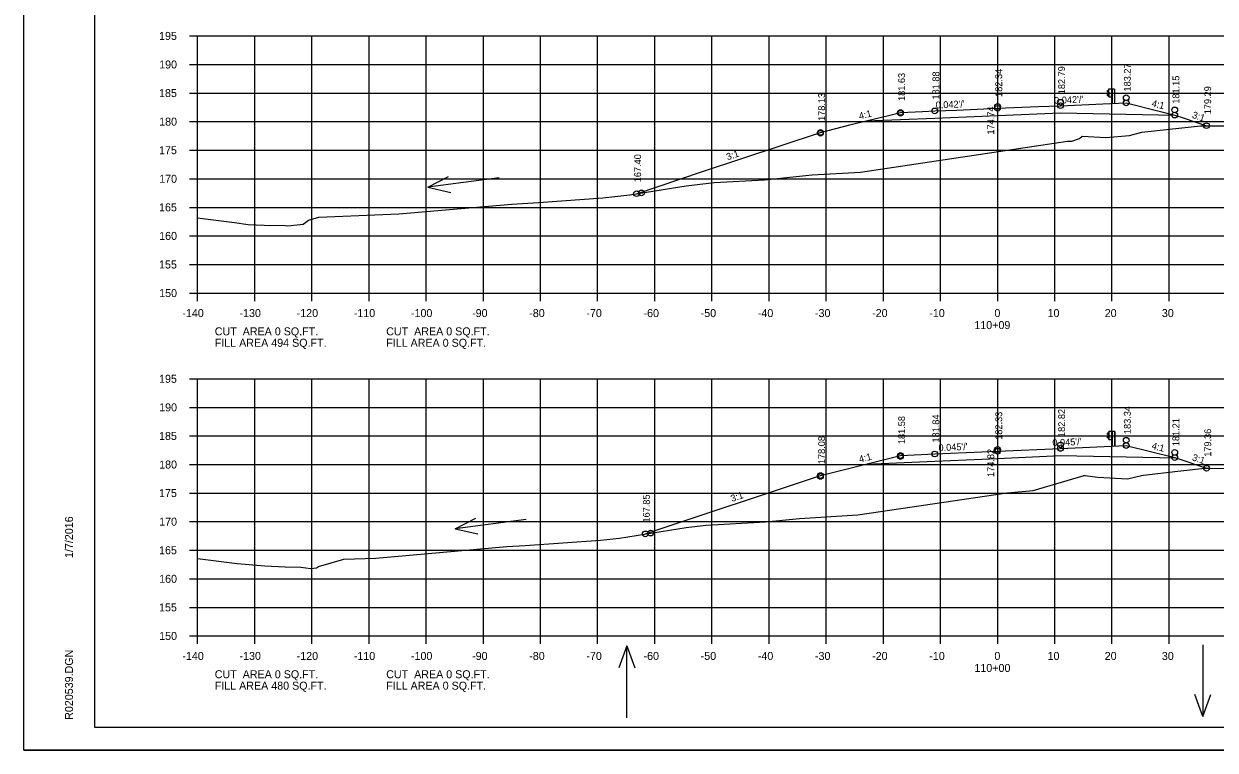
# Model space of a CAD drawing. Extents: x 915787 to 919910, y 133456 to 136717.
# Drawn here: x 916243.6 to 916452, y 134309.4 to 134436.5 of the extents above; entities that cross this region are included whole.
import ezdxf

# ---------------------------------------------------------------- set-up
doc = ezdxf.new("R2010")
doc.units = 0
for name, color, linetype in [('R_Axis', 7, 'Continuous'), ('R_Axis Annot', 7, 'Continuous'), ('R_Border', 7, 'Continuous'), ('R_Border Notes', 7, 'Continuous'), ('R_Exist Surface', 7, 'Continuous'), ('R_Fin Surface', 7, 'Continuous'), ('R_Grid', 7, 'Continuous'), ('R_No Plot', 7, 'Continuous'), ('R_Proposed Road', 7, 'Continuous'), ('R_Water Annot', 7, 'Continuous'), ('R_Xsect Elev', 7, 'Continuous'), ('R_Xsect Slope', 7, 'Continuous')]:
    doc.layers.add(name, color=color, linetype=linetype)

msp = doc.modelspace()

# ---------------------------------------------------------------- linework, layer by layer
at = {"layer": 'R_Axis'}
for p, q in [((916272.58, 134434.37), (916273.98, 134434.37)), ((916273.98, 134389.37), (916273.98, 134434.37)), ((916272.58, 134429.37), (916273.98, 134429.37)), ((916272.58, 134424.37), (916273.98, 134424.37)), ((916272.58, 134419.37), (916273.98, 134419.37)), ((916272.58, 134414.37), (916273.98, 134414.37)), ((916272.58, 134409.37), (916273.98, 134409.37)), ((916272.58, 134404.37), (916273.98, 134404.37)), ((916272.58, 134399.37), (916273.98, 134399.37)), ((916272.58, 134394.37), (916273.98, 134394.37)), ((916272.58, 134389.37), (916273.98, 134389.37)), ((916273.98, 134389.37), (916553.98, 134389.37)), ((916273.98, 134387.97), (916273.98, 134389.37)), ((916283.98, 134387.97), (916283.98, 134389.37)), ((916293.98, 134387.97), (916293.98, 134389.37)), ((916303.98, 134387.97), (916303.98, 134389.37)), ((916313.98, 134387.97), (916313.98, 134389.37)), ((916323.98, 134387.97), (916323.98, 134389.37)), ((916333.98, 134387.97), (916333.98, 134389.37)), ((916343.98, 134387.97), (916343.98, 134389.37)), ((916353.98, 134387.97), (916353.98, 134389.37)), ((916363.98, 134387.97), (916363.98, 134389.37)), ((916373.98, 134387.97), (916373.98, 134389.37)), ((916383.98, 134387.97), (916383.98, 134389.37)), ((916393.98, 134387.97), (916393.98, 134389.37)), ((916403.98, 134387.97), (916403.98, 134389.37)), ((916413.98, 134387.97), (916413.98, 134389.37)), ((916423.98, 134387.97), (916423.98, 134389.37)), ((916433.98, 134387.97), (916433.98, 134389.37)), ((916443.98, 134387.97), (916443.98, 134389.37)), ((916272.58, 134374.37), (916273.98, 134374.37)), ((916273.98, 134329.37), (916273.98, 134374.37)), ((916272.58, 134369.37), (916273.98, 134369.37)), ((916272.58, 134364.37), (916273.98, 134364.37)), ((916272.58, 134359.37), (916273.98, 134359.37)), ((916272.58, 134354.37), (916273.98, 134354.37)), ((916272.58, 134349.37), (916273.98, 134349.37)), ((916272.58, 134344.37), (916273.98, 134344.37)), ((916272.58, 134339.37), (916273.98, 134339.37)), ((916272.58, 134334.37), (916273.98, 134334.37)), ((916272.58, 134329.37), (916273.98, 134329.37)), ((916273.98, 134329.37), (916553.98, 134329.37)), ((916273.98, 134327.97), (916273.98, 134329.37)), ((916283.98, 134327.97), (916283.98, 134329.37)), ((916293.98, 134327.97), (916293.98, 134329.37)), ((916303.98, 134327.97), (916303.98, 134329.37)), ((916313.98, 134327.97), (916313.98, 134329.37)), ((916323.98, 134327.97), (916323.98, 134329.37)), ((916333.98, 134327.97), (916333.98, 134329.37)), ((916343.98, 134327.97), (916343.98, 134329.37)), ((916353.98, 134327.97), (916353.98, 134329.37)), ((916363.98, 134327.97), (916363.98, 134329.37)), ((916373.98, 134327.97), (916373.98, 134329.37)), ((916383.98, 134327.97), (916383.98, 134329.37)), ((916393.98, 134327.97), (916393.98, 134329.37)), ((916403.98, 134327.97), (916403.98, 134329.37)), ((916413.98, 134327.97), (916413.98, 134329.37)), ((916423.98, 134327.97), (916423.98, 134329.37)), ((916433.98, 134327.97), (916433.98, 134329.37)), ((916443.98, 134327.97), (916443.98, 134329.37))]:
    msp.add_line(p, q, dxfattribs=at)
at = {"layer": 'R_Border'}
for p, q in [((916255.98, 134313.37), (916255.98, 134518.83)), ((916255.98, 134313.37), (916255.98, 134313.37)), ((916572.16, 134313.37), (916255.98, 134313.37))]:
    msp.add_line(p, q, dxfattribs=at)
at = {"layer": 'R_Exist Surface'}
for points in [[(916273.98, 134402.53), (916280.41, 134401.69), (916282.85, 134401.35), (916285.65, 134401.27), (916289.3, 134401.22), (916289.75, 134401.16), (916292.42, 134401.45), (916293.41, 134402.15), (916295.18, 134402.65), (916309.18, 134403.23), (916328.94, 134404.94), (916333.63, 134405.24), (916344.9, 134406.02), (916349.64, 134406.57), (916359.49, 134408.14), (916364.37, 134408.7), (916373.17, 134409.2), (916381.49, 134410.04), (916389.97, 134410.53), (916426.22, 134415.93), (916426.93, 134415.98), (916428.32, 134416.39), (916428.75, 134416.83), (916432.88, 134416.58), (916437.03, 134416.95), (916439.21, 134417.53), (916444.03, 134418.04), (916449.5, 134418.66), (916455.2, 134418.65)], [(916273.98, 134342.94), (916280.91, 134342.07), (916285.77, 134341.65), (916289.29, 134341.45), (916292.03, 134341.42), (916293.81, 134341.16), (916294.8, 134341.27), (916295.16, 134341.53), (916299.56, 134342.78), (916305.17, 134343.01), (916328.09, 134345), (916331.27, 134345.2), (916344.49, 134346.12), (916347.82, 134346.5), (916359.45, 134348.36), (916362.89, 134348.76), (916373.34, 134349.35), (916379.3, 134349.95), (916389.49, 134350.54), (916415.63, 134354.43), (916420.18, 134354.8), (916429.1, 134357.45), (916429.13, 134357.48), (916429.26, 134357.45), (916431.51, 134357.13), (916436.67, 134356.86), (916439.16, 134357.44), (916439.51, 134357.51), (916445.5, 134358.19), (916450.19, 134358.73), (916450.82, 134358.72), (916456.38, 134358.62)]]:
    msp.add_lwpolyline(points, dxfattribs=at)
at = {"layer": 'R_Fin Surface'}
for points in [[(916350.78, 134406.76), (916362.34, 134410.62), (916382.97, 134417.49), (916388.1, 134418.78), (916390.97, 134419.49), (916394.85, 134420.46), (916396.97, 134420.99), (916400.83, 134421.16), (916402.97, 134421.24), (916406.86, 134421.4), (916413.97, 134421.7), (916421.04, 134422), (916424.97, 134422.16), (916432.36, 134422.47), (916436.47, 134422.64), (916442.47, 134421.14), (916444.97, 134420.51), (916444.99, 134420.51), (916446.59, 134419.97), (916450.53, 134418.66)], [(916390.97, 134419.49), (916402.97, 134419.99), (916413.97, 134420.45), (916424.97, 134420.91), (916444.99, 134420.51)], [(916352.31, 134347.22), (916382.97, 134357.44), (916390.89, 134359.42), (916396.97, 134360.94), (916402.97, 134361.21), (916413.97, 134361.7), (916424.97, 134362.19), (916436.47, 134362.7), (916444.97, 134360.58), (916445.14, 134360.54), (916450.52, 134358.73)], [(916390.89, 134359.42), (916402.97, 134359.96), (916413.97, 134360.45), (916424.97, 134360.94), (916445.14, 134360.54)]]:
    msp.add_lwpolyline(points, dxfattribs=at)
at = {"layer": 'R_Grid'}
for p, q in [((916273.98, 134434.37), (916553.98, 134434.37)), ((916273.98, 134389.37), (916273.98, 134434.37)), ((916283.98, 134389.37), (916283.98, 134434.37)), ((916293.98, 134389.37), (916293.98, 134434.37)), ((916303.98, 134389.37), (916303.98, 134434.37)), ((916313.98, 134389.37), (916313.98, 134434.37)), ((916323.98, 134389.37), (916323.98, 134434.37)), ((916333.98, 134389.37), (916333.98, 134434.37)), ((916343.98, 134389.37), (916343.98, 134434.37)), ((916353.98, 134389.37), (916353.98, 134434.37)), ((916363.98, 134389.37), (916363.98, 134434.37)), ((916373.98, 134389.37), (916373.98, 134434.37)), ((916383.98, 134389.37), (916383.98, 134434.37)), ((916393.98, 134389.37), (916393.98, 134434.37)), ((916403.98, 134389.37), (916403.98, 134434.37)), ((916413.98, 134389.37), (916413.98, 134434.37)), ((916423.98, 134389.37), (916423.98, 134434.37)), ((916433.98, 134389.37), (916433.98, 134434.37)), ((916443.98, 134389.37), (916443.98, 134434.37)), ((916273.98, 134429.37), (916553.98, 134429.37)), ((916273.98, 134424.37), (916553.98, 134424.37)), ((916273.98, 134419.37), (916553.98, 134419.37)), ((916273.98, 134414.37), (916553.98, 134414.37)), ((916273.98, 134409.37), (916553.98, 134409.37)), ((916273.98, 134404.37), (916553.98, 134404.37)), ((916273.98, 134399.37), (916553.98, 134399.37)), ((916273.98, 134394.37), (916553.98, 134394.37)), ((916273.98, 134389.37), (916553.98, 134389.37)), ((916273.98, 134374.37), (916553.98, 134374.37)), ((916273.98, 134329.37), (916273.98, 134374.37)), ((916283.98, 134329.37), (916283.98, 134374.37)), ((916293.98, 134329.37), (916293.98, 134374.37)), ((916303.98, 134329.37), (916303.98, 134374.37)), ((916313.98, 134329.37), (916313.98, 134374.37)), ((916323.98, 134329.37), (916323.98, 134374.37)), ((916333.98, 134329.37), (916333.98, 134374.37)), ((916343.98, 134329.37), (916343.98, 134374.37)), ((916353.98, 134329.37), (916353.98, 134374.37)), ((916363.98, 134329.37), (916363.98, 134374.37)), ((916373.98, 134329.37), (916373.98, 134374.37)), ((916383.98, 134329.37), (916383.98, 134374.37)), ((916393.98, 134329.37), (916393.98, 134374.37)), ((916403.98, 134329.37), (916403.98, 134374.37)), ((916413.98, 134329.37), (916413.98, 134374.37)), ((916423.98, 134329.37), (916423.98, 134374.37)), ((916433.98, 134329.37), (916433.98, 134374.37)), ((916443.98, 134329.37), (916443.98, 134374.37)), ((916273.98, 134369.37), (916553.98, 134369.37)), ((916273.98, 134364.37), (916553.98, 134364.37)), ((916273.98, 134359.37), (916553.98, 134359.37)), ((916273.98, 134354.37), (916553.98, 134354.37)), ((916273.98, 134349.37), (916553.98, 134349.37)), ((916273.98, 134344.37), (916553.98, 134344.37)), ((916273.98, 134339.37), (916553.98, 134339.37)), ((916273.98, 134334.37), (916553.98, 134334.37)), ((916273.98, 134329.37), (916553.98, 134329.37))]:
    msp.add_line(p, q, dxfattribs=at)
at = {"layer": 'R_No Plot'}
msp.add_line((916243.57, 134309.39), (916576.91, 134309.39), dxfattribs=at)
for points in [[(916243.57, 134522.72), (916576.91, 134522.72), (916576.91, 134309.38), (916243.57, 134309.38)], [(916489.9, 134518.83), (916489.9, 134508.95), (916525.63, 134508.95), (916525.63, 134506.03), (916548.83, 134506.03), (916548.83, 134482.81), (916572.16, 134482.81), (916572.16, 134313.37), (916255.98, 134313.37), (916255.98, 134518.83)]]:
    msp.add_lwpolyline(points, close=True, dxfattribs=at)
for centre in [(916436.47, 134423.55), (916396.97, 134420.99), (916396.97, 134420.83), (916402.97, 134421.24), (916402.97, 134421.24), (916413.97, 134422), (916413.97, 134421.7), (916424.97, 134422.76), (916424.97, 134422.16), (916436.47, 134422.64), (916444.97, 134421.42), (916444.97, 134420.51), (916382.97, 134417.49), (916382.97, 134417.33), (916450.53, 134418.66), (916350.78, 134406.76), (916351.66, 134406.89), (916424.97, 134362.79), (916436.47, 134363.61), (916436.47, 134362.7), (916396.97, 134360.94), (916396.97, 134360.78), (916402.97, 134361.21), (916402.97, 134361.21), (916413.97, 134362), (916413.97, 134361.7), (916424.97, 134362.19), (916444.97, 134361.49), (916444.97, 134360.58), (916450.54, 134358.72), (916382.97, 134357.44), (916382.97, 134357.28), (916352.31, 134347.22), (916353.24, 134347.37)]:
    msp.add_circle(centre, 0.5, dxfattribs=at)
at = {"layer": 'R_Proposed Road'}
for p, q in [((916433.28, 134423.91), (916433.15, 134424.02)), ((916433.16, 134424.75), (916433.29, 134424.86)), ((916433.33, 134424.51), (916433.16, 134424.61)), ((916433.17, 134424.74), (916433.3, 134424.84)), ((916433.34, 134424.53), (916433.17, 134424.63)), ((916433.29, 134423.92), (916433.17, 134424.03)), ((916433.18, 134424.17), (916433.34, 134424.27)), ((916433.19, 134424.15), (916433.35, 134424.25)), ((916433.39, 134423.85), (916433.28, 134423.91)), ((916433.29, 134424.86), (916433.4, 134424.92)), ((916433.4, 134423.87), (916433.29, 134423.92)), ((916433.3, 134424.84), (916433.39, 134424.89)), ((916433.37, 134424.33), (916433.37, 134424.46)), ((916433.39, 134424.33), (916433.39, 134424.46)), ((916433.43, 134423.71), (916433.43, 134425.07)), ((916433.44, 134424.33), (916433.44, 134424.45)), ((916433.44, 134424.45), (916433.49, 134424.45)), ((916433.44, 134424.42), (916433.49, 134424.42)), ((916433.44, 134424.36), (916433.49, 134424.36)), ((916433.44, 134424.36), (916433.49, 134424.36)), ((916433.44, 134424.33), (916433.49, 134424.33)), ((916433.5, 134424.34), (916433.5, 134424.44)), ((916433.92, 134424.77), (916433.87, 134424.77)), ((916433.87, 134424.77), (916433.87, 134424.64)), ((916433.87, 134424.7), (916433.93, 134424.7)), ((916433.92, 134424.64), (916433.87, 134424.64)), ((916433.87, 134423.96), (916433.87, 134424.08)), ((916433.87, 134424.08), (916433.92, 134424.08)), ((916433.87, 134424.02), (916433.93, 134424.02)), ((916433.87, 134423.96), (916433.92, 134423.96)), ((916433.93, 134425.07), (916433.94, 134425.07)), ((916433.93, 134425.07), (916434, 134425.07)), ((916433.93, 134423.71), (916433.96, 134423.71)), ((916433.96, 134422.56), (916433.96, 134425.07)), ((916434, 134424.65), (916434, 134424.77)), ((916434, 134424.77), (916434.05, 134424.77)), ((916434, 134424.74), (916434.05, 134424.74)), ((916434, 134424.68), (916434.04, 134424.68)), ((916434, 134424.68), (916434.05, 134424.68)), ((916434, 134424.65), (916434.05, 134424.65)), ((916434.01, 134423.96), (916434.01, 134424.08)), ((916434.01, 134424.08), (916434.06, 134424.08)), ((916434.01, 134424.05), (916434.06, 134424.05)), ((916434.01, 134423.99), (916434.05, 134423.99)), ((916434.01, 134423.99), (916434.06, 134423.99)), ((916434.01, 134423.96), (916434.06, 134423.96)), ((916434.05, 134424.66), (916434.05, 134424.76)), ((916434.06, 134423.97), (916434.06, 134424.07)), ((916434.42, 134425.07), (916434.42, 134422.56)), ((916434.45, 134425.07), (916434.45, 134422.56)), ((916433.29, 134364.92), (916433.4, 134364.98)), ((916433.44, 134363.77), (916433.44, 134365.13)), ((916433.93, 134365.14), (916433.94, 134365.14)), ((916433.93, 134365.14), (916434, 134365.14)), ((916433.97, 134362.62), (916433.97, 134365.14)), ((916434.43, 134365.14), (916434.43, 134362.62)), ((916434.46, 134365.14), (916434.46, 134362.62)), ((916433.16, 134364.82), (916433.29, 134364.92)), ((916433.34, 134364.57), (916433.16, 134364.67)), ((916433.29, 134363.97), (916433.16, 134364.08)), ((916433.17, 134364.8), (916433.3, 134364.91)), ((916433.3, 134363.99), (916433.17, 134364.1)), ((916433.35, 134364.59), (916433.18, 134364.7)), ((916433.19, 134364.24), (916433.34, 134364.34)), ((916433.2, 134364.22), (916433.35, 134364.32)), ((916433.4, 134363.91), (916433.29, 134363.97)), ((916433.3, 134364.91), (916433.4, 134364.96)), ((916433.41, 134363.93), (916433.3, 134363.99)), ((916433.37, 134364.39), (916433.37, 134364.52)), ((916433.4, 134364.39), (916433.39, 134364.52)), ((916433.45, 134364.39), (916433.45, 134364.51)), ((916433.45, 134364.51), (916433.5, 134364.51)), ((916433.45, 134364.48), (916433.5, 134364.48)), ((916433.45, 134364.42), (916433.49, 134364.42)), ((916433.45, 134364.42), (916433.5, 134364.42)), ((916433.45, 134364.39), (916433.5, 134364.39)), ((916433.5, 134364.4), (916433.5, 134364.5)), ((916433.93, 134364.83), (916433.88, 134364.83)), ((916433.88, 134364.83), (916433.88, 134364.71)), ((916433.88, 134364.77), (916433.94, 134364.77)), ((916433.93, 134364.71), (916433.88, 134364.71)), ((916433.88, 134364.02), (916433.88, 134364.15)), ((916433.88, 134364.15), (916433.93, 134364.15)), ((916433.88, 134364.08), (916433.94, 134364.08)), ((916433.88, 134364.02), (916433.93, 134364.02)), ((916433.94, 134363.77), (916433.97, 134363.77)), ((916434, 134364.71), (916434, 134364.84)), ((916434, 134364.84), (916434.05, 134364.84)), ((916434, 134364.81), (916434.05, 134364.81)), ((916434, 134364.74), (916434.05, 134364.74)), ((916434, 134364.74), (916434.05, 134364.74)), ((916434, 134364.71), (916434.05, 134364.71)), ((916434.01, 134364.02), (916434.01, 134364.15)), ((916434.01, 134364.15), (916434.06, 134364.15)), ((916434.01, 134364.12), (916434.06, 134364.12)), ((916434.01, 134364.05), (916434.06, 134364.05)), ((916434.01, 134364.05), (916434.06, 134364.05)), ((916434.01, 134364.02), (916434.06, 134364.02)), ((916434.06, 134364.73), (916434.06, 134364.82)), ((916434.07, 134364.04), (916434.07, 134364.13))]:
    msp.add_line(p, q, dxfattribs=at)
for points in [[(916433.4, 134425.07), (916433.41, 134423.71), (916433.93, 134423.71), (916433.93, 134425.07)], [(916433.44, 134424.47), (916433.44, 134424.3), (916433.43, 134424.3), (916433.43, 134424.47)], [(916433.5, 134424.42), (916433.5, 134424.36), (916433.53, 134424.36), (916433.53, 134424.42)], [(916433.87, 134424.77), (916433.87, 134424.64), (916433.93, 134424.64), (916433.93, 134424.77)], [(916433.87, 134424.08), (916433.87, 134423.96), (916433.93, 134423.96), (916433.93, 134424.08)], [(916434, 134424.79), (916434, 134424.62), (916433.99, 134424.62), (916433.99, 134424.79)], [(916434.01, 134424.1), (916434.01, 134423.93), (916434, 134423.93), (916434, 134424.1)], [(916434.06, 134424.74), (916434.06, 134424.68), (916434.08, 134424.68), (916434.08, 134424.74)], [(916434.07, 134424.05), (916434.07, 134423.99), (916434.09, 134423.99), (916434.09, 134424.05)], [(916433.41, 134365.14), (916433.41, 134363.77), (916433.94, 134363.77), (916433.93, 134365.14)], [(916433.45, 134364.53), (916433.45, 134364.37), (916433.44, 134364.37), (916433.44, 134364.53)], [(916433.51, 134364.48), (916433.51, 134364.42), (916433.53, 134364.42), (916433.53, 134364.48)], [(916433.88, 134364.83), (916433.88, 134364.71), (916433.93, 134364.71), (916433.93, 134364.83)], [(916433.88, 134364.15), (916433.88, 134364.02), (916433.93, 134364.02), (916433.93, 134364.15)], [(916434.01, 134364.86), (916434.01, 134364.69), (916434, 134364.69), (916434, 134364.86)], [(916434.02, 134364.17), (916434.02, 134364), (916434.01, 134364), (916434.01, 134364.17)], [(916434.06, 134364.8), (916434.06, 134364.74), (916434.09, 134364.74), (916434.09, 134364.8)], [(916434.07, 134364.12), (916434.07, 134364.05), (916434.1, 134364.05), (916434.1, 134364.12)]]:
    msp.add_lwpolyline(points, close=True, dxfattribs=at)
for points in [[(916434.45, 134425.07), (916434, 134425.07), (916434, 134422.56)], [(916434.46, 134365.14), (916434, 134365.14), (916434, 134362.62)]]:
    msp.add_lwpolyline(points, dxfattribs=at)
for centre, radius, start, end in [((916433.2, 134424.69), 0.0856, 122.0217, 240.7501), ((916433.24, 134424.08), 0.109, 120.88, 214.7816), ((916433.2, 134424.69), 0.062, 122.0217, 240.7501), ((916433.24, 134424.08), 0.0854, 120.88, 214.7816), ((916433.3, 134424.45), 0.0622, 4.9556, 61.894), ((916433.37, 134424.38), 0.0453, 93.9303, 257.0446), ((916433.3, 134424.45), 0.0865, 4.9556, 61.894), ((916433.32, 134424.32), 0.0462, 293.1464, 8.2196), ((916433.32, 134424.32), 0.0703, 293.1464, 8.2196), ((916433.48, 134424.43), 0.022, 317.7756, 45.4255), ((916433.41, 134424.39), 0.0922, 339.7423, 20.2577), ((916433.47, 134424.34), 0.025, 323.3766, 39.0666), ((916434.03, 134424.76), 0.022, 317.7756, 45.4255), ((916433.96, 134424.71), 0.0922, 339.7423, 20.2577), ((916434.03, 134424.66), 0.025, 323.3766, 39.0666), ((916434.04, 134424.07), 0.022, 317.7756, 45.4255), ((916433.97, 134424.02), 0.0922, 339.7423, 20.2577), ((916434.04, 134423.97), 0.025, 323.3766, 39.0666), ((916433.21, 134364.75), 0.0856, 122.0217, 240.7501), ((916433.24, 134364.15), 0.109, 120.88, 214.7816), ((916433.21, 134364.75), 0.062, 122.0217, 240.7501), ((916433.24, 134364.15), 0.0854, 120.88, 214.7816), ((916433.38, 134364.45), 0.0453, 93.9303, 257.0446), ((916433.31, 134364.51), 0.0622, 4.9556, 61.894), ((916433.33, 134364.38), 0.0462, 293.1464, 8.2196), ((916433.31, 134364.51), 0.0865, 4.9556, 61.894), ((916433.33, 134364.38), 0.0703, 293.1464, 8.2196), ((916433.48, 134364.5), 0.022, 317.7756, 45.4255), ((916433.41, 134364.45), 0.0922, 339.7423, 20.2577), ((916433.48, 134364.4), 0.025, 323.3766, 39.0666), ((916434.04, 134364.82), 0.022, 317.7756, 45.4255), ((916433.97, 134364.77), 0.0922, 339.7423, 20.2577), ((916434.03, 134364.73), 0.025, 323.3766, 39.0666), ((916434.05, 134364.13), 0.022, 317.7756, 45.4255), ((916433.98, 134364.08), 0.0922, 339.7423, 20.2577), ((916434.04, 134364.04), 0.025, 323.3766, 39.0666)]:
    msp.add_arc(centre, radius, start, end, dxfattribs=at)
at = {"layer": 'R_Water Annot'}
for p, q in [((916314.27, 134407.88), (916317.91, 134409.76)), ((916326.74, 134409.51), (916314.27, 134407.88)), ((916314.27, 134407.88), (916318.27, 134406.99)), ((916319.02, 134348.12), (916322.65, 134350.01)), ((916331.48, 134349.75), (916319.02, 134348.12)), ((916319.02, 134348.12), (916323.01, 134347.23)), ((916349.07, 134327.63), (916347.67, 134323.79)), ((916349.07, 134315.06), (916349.07, 134327.63)), ((916349.07, 134327.63), (916350.47, 134323.79)), ((916449.86, 134327.82), (916449.86, 134315.25)), ((916449.86, 134315.25), (916448.46, 134319.1)), ((916449.86, 134315.25), (916451.26, 134319.1))]:
    msp.add_line(p, q, dxfattribs=at)

# ---------------------------------------------------------------- texts
at = {"layer": 'R_Axis Annot'}
for s, p in [('195', (916267.23, 134433.67)), ('190', (916267.25, 134428.67)), ('185', (916267.23, 134423.67)), ('180', (916267.25, 134418.67)), ('175', (916267.23, 134413.67)), ('170', (916267.25, 134408.67)), ('165', (916267.23, 134403.67)), ('160', (916267.25, 134398.67)), ('155', (916267.23, 134393.67)), ('150', (916267.25, 134388.67)), ('-140', (916271.31, 134385.17)), ('-130', (916281.31, 134385.17)), ('-120', (916291.31, 134385.17)), ('-110', (916301.31, 134385.17)), ('-100', (916311.31, 134385.17)), ('-90', (916322.01, 134385.17)), ('-80', (916332.01, 134385.17)), ('-70', (916342.01, 134385.17)), ('-60', (916352.01, 134385.17)), ('-50', (916362.01, 134385.17)), ('-40', (916372.01, 134385.17)), ('-30', (916382.01, 134385.17)), ('-20', (916392.01, 134385.17)), ('-10', (916402.01, 134385.17)), ('0', (916413.41, 134385.17)), ('10', (916422.71, 134385.17)), ('20', (916432.71, 134385.17)), ('30', (916442.71, 134385.17)), ('110+09', (916409.9, 134383.07)), ('195', (916267.23, 134373.67)), ('190', (916267.25, 134368.67)), ('185', (916267.23, 134363.67)), ('180', (916267.25, 134358.67)), ('175', (916267.23, 134353.67)), ('170', (916267.25, 134348.67)), ('165', (916267.23, 134343.67)), ('160', (916267.25, 134338.67)), ('155', (916267.23, 134333.67)), ('150', (916267.25, 134328.67)), ('-140', (916271.31, 134325.17)), ('-130', (916281.31, 134325.17)), ('-120', (916291.31, 134325.17)), ('-110', (916301.31, 134325.17)), ('-100', (916311.31, 134325.17)), ('-90', (916322.01, 134325.17)), ('-80', (916332.01, 134325.17)), ('-70', (916342.01, 134325.17)), ('-60', (916352.01, 134325.17)), ('-50', (916362.01, 134325.17)), ('-40', (916372.01, 134325.17)), ('-30', (916382.01, 134325.17)), ('-20', (916392.01, 134325.17)), ('-10', (916402.01, 134325.17)), ('0', (916413.41, 134325.17)), ('10', (916422.71, 134325.17)), ('20', (916432.71, 134325.17)), ('30', (916442.71, 134325.17)), ('110+00', (916409.91, 134323.07))]:
    msp.add_text(s, height=1.4, dxfattribs=at).set_placement(p)
at = {"layer": 'R_Border'}
for s, p in [('1/7/2016', (916252.17, 134343.01)), ('R020539.DGN', (916252.17, 134314.69))]:
    msp.add_text(s, height=1.4, rotation=90, dxfattribs=at).set_placement(p)
at = {"layer": 'R_Border Notes'}
for s, p in [('CUT  AREA 0 SQ.FT.', (916276.98, 134381.97)), ('CUT  AREA 0 SQ.FT.', (916306.98, 134381.97)), ('FILL AREA 494 SQ.FT.', (916276.98, 134379.97)), ('FILL AREA 0 SQ.FT.', (916306.98, 134379.97)), ('CUT  AREA 0 SQ.FT.', (916276.98, 134321.97)), ('CUT  AREA 0 SQ.FT.', (916306.98, 134321.97)), ('FILL AREA 480 SQ.FT.', (916276.98, 134319.97)), ('FILL AREA 0 SQ.FT.', (916306.98, 134319.97))]:
    msp.add_text(s, height=1.4, dxfattribs=at).set_placement(p)
at = {"layer": 'R_Xsect Elev'}
for s, p in [('181.63', (916397.77, 134422.99)), ('181.88', (916403.77, 134423.24)), ('182.34', (916414.77, 134423.7)), ('182.79', (916425.77, 134424.16)), ('183.27', (916437.27, 134424.64)), ('181.15', (916445.77, 134422.51)), ('179.29', (916451.33, 134420.66)), ('178.13', (916383.77, 134419.49)), ('174.74', (916413.38, 134417.1)), ('167.40', (916351.58, 134408.76)), ('183.34', (916437.27, 134364.7)), ('181.58', (916397.77, 134362.94)), ('181.84', (916403.77, 134363.21)), ('182.33', (916414.77, 134363.7)), ('182.82', (916425.77, 134364.19)), ('181.21', (916445.77, 134362.58)), ('179.36', (916451.34, 134360.72)), ('178.08', (916383.77, 134359.44)), ('174.82', (916413.38, 134357.19)), ('167.85', (916353.11, 134349.22))]:
    msp.add_text(s, height=1.2, rotation=90, dxfattribs=at).set_placement(p)
at = {"layer": 'R_Xsect Slope'}
for s, rotation, p in [("0.042'/'", 2.3859, (916423.89, 134422.48)), ('4:1', 14.0363, (916389.85, 134419.73)), ("0.042'/'", 2.3859, (916403.15, 134421.67)), ('4:1', 345.9637, (916440.84, 134422.06)), ('3:1', 341.565, (916447.91, 134420.06)), ('3:1', 18.435, (916366.72, 134412.6)), ("0.045'/'", 2.5521, (916403.65, 134361.7)), ("0.045'/'", 2.5521, (916423.58, 134362.57)), ('4:1', 345.9638, (916440.85, 134362.13)), ('4:1', 14.0362, (916389.85, 134359.68)), ('3:1', 341.5651, (916447.91, 134360.13)), ('3:1', 18.4349, (916367.48, 134352.81))]:
    msp.add_text(s, height=1.2, rotation=rotation, dxfattribs=at).set_placement(p)

doc.saveas('drawing.dxf')
